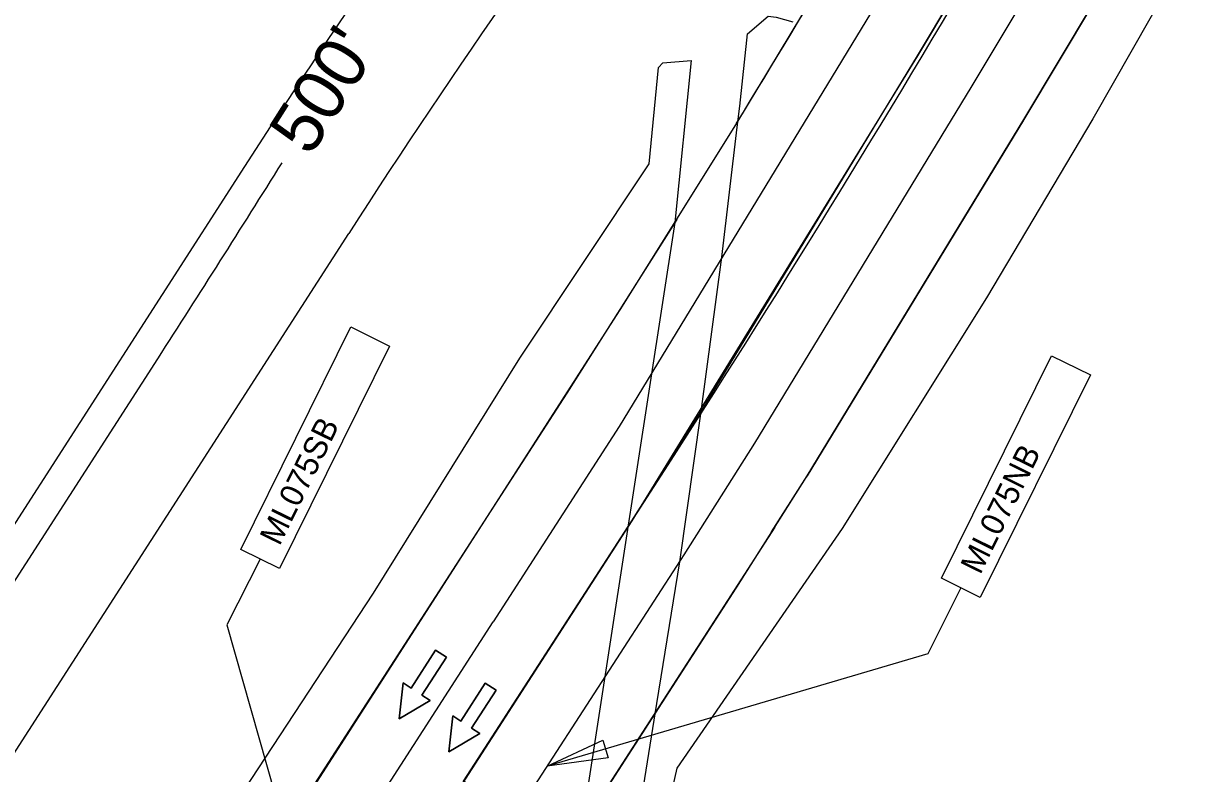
# Model space of a CAD drawing. Extents: x 14104283 to 14129344, y 8637090 to 8673339.
# Drawn here: x 14119391.8 to 14119617.1, y 8669375.5 to 8669521 of the extents above; entities that cross this region are included whole.
import ezdxf

# ---------------------------------------------------------------- set-up
doc = ezdxf.new("R2010")
doc.units = 0
for name, color, linetype in [('dsnPaintExistingBrokenLaneLineWhite', 7, 'Continuous'), ('dsnPaintExistingDoubleCenterYellow', 7, 'Continuous'), ('dsnPaintExistingEdgeLineRightWhite', 7, 'Continuous'), ('dsnShadingPaved', 7, 'Continuous'), ('dsnStdLabel', 7, 'Continuous'), ('dsnStgShadingPrevPav', 7, 'Continuous'), ('Level 2', 7, 'Continuous'), ('Level 5', 7, 'Continuous'), ('Text', 7, 'Continuous')]:
    doc.layers.add(name, color=color, linetype=linetype)

msp = doc.modelspace()

# ---------------------------------------------------------------- linework, layer by layer
at = {"layer": 'dsnPaintExistingBrokenLaneLineWhite'}
msp.add_line((14119409.98, 8669291.54), (14119482.88, 8669404.98), dxfattribs=at)
for points in [[(14119581.73, 8669565.18), (14119507.3, 8669442.79), (14119482.88, 8669404.98)], [(14119602.41, 8669553.65), (14119575.44, 8669508.54), (14119533.52, 8669439.61), (14119519.81, 8669417.96), (14119487.25, 8669367.53)]]:
    msp.add_lwpolyline(points, dxfattribs=at)
at = {"layer": 'dsnPaintExistingDoubleCenterYellow'}
for p, q in [((14119494.22, 8669400.39), (14119517.38, 8669436.28)), ((14119403.44, 8669259.76), (14119494.22, 8669400.39))]:
    msp.add_line(p, q, dxfattribs=at)
msp.add_arc((14117116.91, 8670980.36), 2854.2, 327.24958, 332.18395, dxfattribs=at)
at = {"layer": 'dsnPaintExistingEdgeLineRightWhite'}
for p, q in [((14119329.79, 8669101.47), (14119537.52, 8669423.28)), ((14119472.8, 8669411.49), (14119412.15, 8669317.07))]:
    msp.add_line(p, q, dxfattribs=at)
for points in [[(14119571.48, 8669571.41), (14119550.92, 8669536.23), (14119530.04, 8669501.61), (14119507.87, 8669466.11), (14119472.8, 8669411.49)], [(14119536.82, 8669422.39), (14119543.72, 8669433.28), (14119585.72, 8669502.34), (14119612.71, 8669547.49)]]:
    msp.add_lwpolyline(points, dxfattribs=at)
at = {"layer": 'dsnShadingPaved'}
for p, q in [((14119497.21, 8669449.29), (14119518.52, 8669482.93)), ((14119155.5, 8668919.9), (14119497.22, 8669449.29)), ((14119509.78, 8669424.5), (14119403.44, 8669259.76))]:
    msp.add_line(p, q, dxfattribs=at)
for points in [[(14119477.17, 8669374.04), (14119509.75, 8669424.51), (14119523.21, 8669445.75), (14119565.12, 8669514.66), (14119591.92, 8669559.48), (14119612.71, 8669547.49), (14119585.72, 8669502.34), (14119585.63, 8669502.18), (14119543.72, 8669433.28), (14119543.48, 8669432.9), (14119530.02, 8669411.67), (14119529.92, 8669411.5), (14119497.33, 8669361.02), (14119477.17, 8669374.04)], [(14119477.17, 8669374.04), (14119509.75, 8669424.51), (14119523.21, 8669445.75), (14119565.12, 8669514.66), (14119591.92, 8669559.48), (14119612.71, 8669547.49), (14119585.72, 8669502.34), (14119585.63, 8669502.18), (14119543.72, 8669433.28), (14119543.48, 8669432.9), (14119530.02, 8669411.67), (14119529.92, 8669411.5), (14119497.33, 8669361.02), (14119477.17, 8669374.04)], [(14119591.92, 8669559.48), (14119565.12, 8669514.66), (14119509.75, 8669424.51)]]:
    msp.add_lwpolyline(points, dxfattribs=at)
msp.add_arc((14117117.1, 8670980.68), 2830.19, 328.49286, 330.12988, dxfattribs=at)
at = {"layer": 'dsnStdLabel'}
for p, q in [((14119434.72, 8669493.24), (14119231.48, 8669177.36)), ((14119251.66, 8669164.37), (14119454.9, 8669480.25)), ((14119324.41, 8669310.66), (14119417.91, 8669455.95))]:
    msp.add_line(p, q, dxfattribs=at)
for centre, radius, start, end in [((14120706.26, 8668675.12), 1512, 137.73115, 147.24256), ((14120706.26, 8668675.12), 1488, 138.43496, 147.24256), ((14116600.71, 8671268.95), 3350.16, 327.23683, 328.00604)]:
    msp.add_arc(centre, radius, start, end, dxfattribs=at)
at = {"layer": 'dsnStgShadingPrevPav'}
for p, q in [((14119530.17, 8669500.82), (14119530.67, 8669504.91)), ((14119518.06, 8669482.38), (14119500.11, 8669365.78)), ((14119512.03, 8669372.94), (14119514.62, 8669389.1))]:
    msp.add_line(p, q, dxfattribs=at)
for points in [[(14119621.71, 8669542.16), (14119599.11, 8669502.43), (14119578.5, 8669467.77), (14119550.51, 8669423.04), (14119518.48, 8669376.61), (14119516.17, 8669366.34), (14119512.13, 8669350.06), (14119507.83, 8669349.42), (14119512.03, 8669372.94)], [(14119530.67, 8669504.91), (14119532.14, 8669518.96), (14119536.17, 8669522.33), (14119537.75, 8669522.14), (14119540.98, 8669521.24)], [(14119513.11, 8669493.72), (14119514.93, 8669512.39), (14119515.74, 8669513.32), (14119521.28, 8669513.76), (14119518.06, 8669482.38)], [(14119514.62, 8669389.1), (14119519.09, 8669416.56), (14119523.21, 8669445.75), (14119527.18, 8669475.65), (14119530.17, 8669500.82)], [(14119403.27, 8669322.21), (14119434.62, 8669372.34), (14119459.73, 8669410.54), (14119488.03, 8669456.05), (14119513.11, 8669493.72)]]:
    msp.add_lwpolyline(points, dxfattribs=at)
at = {"layer": 'Level 2'}
for points in [[(14119473.85, 8669398.09), (14119471.75, 8669399.45), (14119467, 8669392.1), (14119465.43, 8669393.11), (14119464.66, 8669386.17), (14119470.68, 8669389.72), (14119469.1, 8669390.74)], [(14119483.47, 8669391.7), (14119481.37, 8669393.05), (14119476.62, 8669385.7), (14119475.05, 8669386.72), (14119474.28, 8669379.77), (14119480.3, 8669383.33), (14119478.72, 8669384.34)]]:
    msp.add_lwpolyline(points, close=True, dxfattribs=at)
at = {"layer": 'Level 5'}
for points in [[(14119469.1, 8669390.74), (14119470.68, 8669389.72), (14119464.66, 8669386.17), (14119465.43, 8669393.11), (14119467, 8669392.1), (14119471.75, 8669399.45), (14119473.85, 8669398.09), (14119469.1, 8669390.74)], [(14119478.72, 8669384.34), (14119480.3, 8669383.33), (14119474.28, 8669379.77), (14119475.05, 8669386.72), (14119476.62, 8669385.7), (14119481.37, 8669393.05), (14119483.47, 8669391.7), (14119478.72, 8669384.34)]]:
    msp.add_lwpolyline(points, dxfattribs=at)
at = {"layer": 'Text'}
for points in [[(14119433.98, 8669418.98), (14119455.3, 8669462.11), (14119462.83, 8669458.39), (14119441.51, 8669415.26)], [(14119433.98, 8669418.98), (14119455.3, 8669462.11), (14119462.83, 8669458.39), (14119441.51, 8669415.26)], [(14119569.74, 8669413.42), (14119591.07, 8669456.54), (14119598.6, 8669452.82), (14119577.27, 8669409.7)], [(14119569.74, 8669413.42), (14119591.07, 8669456.54), (14119598.6, 8669452.82), (14119577.27, 8669409.7)], [(14119493.34, 8669376.96), (14119504.17, 8669382.01), (14119505.17, 8669378.61)]]:
    msp.add_lwpolyline(points, close=True, dxfattribs=at)
for points in [[(14119437.74, 8669417.12), (14119431.32, 8669404.34), (14119446.81, 8669349.75)], [(14119573.51, 8669411.56), (14119567.09, 8669398.77), (14119493.34, 8669376.96)]]:
    msp.add_lwpolyline(points, dxfattribs=at)

# ---------------------------------------------------------------- texts
at = {"layer": 'dsnStdLabel'}
msp.add_text("500'", height=10, rotation=57.6002, dxfattribs=at).set_placement((14119447.43, 8669494.94))
at = {"layer": 'Text'}
for s, p in [('ML075SB', (14119441.49, 8669419.5)), ('ML075NB', (14119577.26, 8669413.93))]:
    msp.add_text(s, height=4.484, rotation=63.6912, dxfattribs=at).set_placement(p)

doc.saveas('drawing.dxf')
